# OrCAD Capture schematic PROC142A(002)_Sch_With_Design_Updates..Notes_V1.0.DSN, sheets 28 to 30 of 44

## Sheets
28 27. XDS110 DEBUGGER: size C; title: XDS110 DEBUGGER
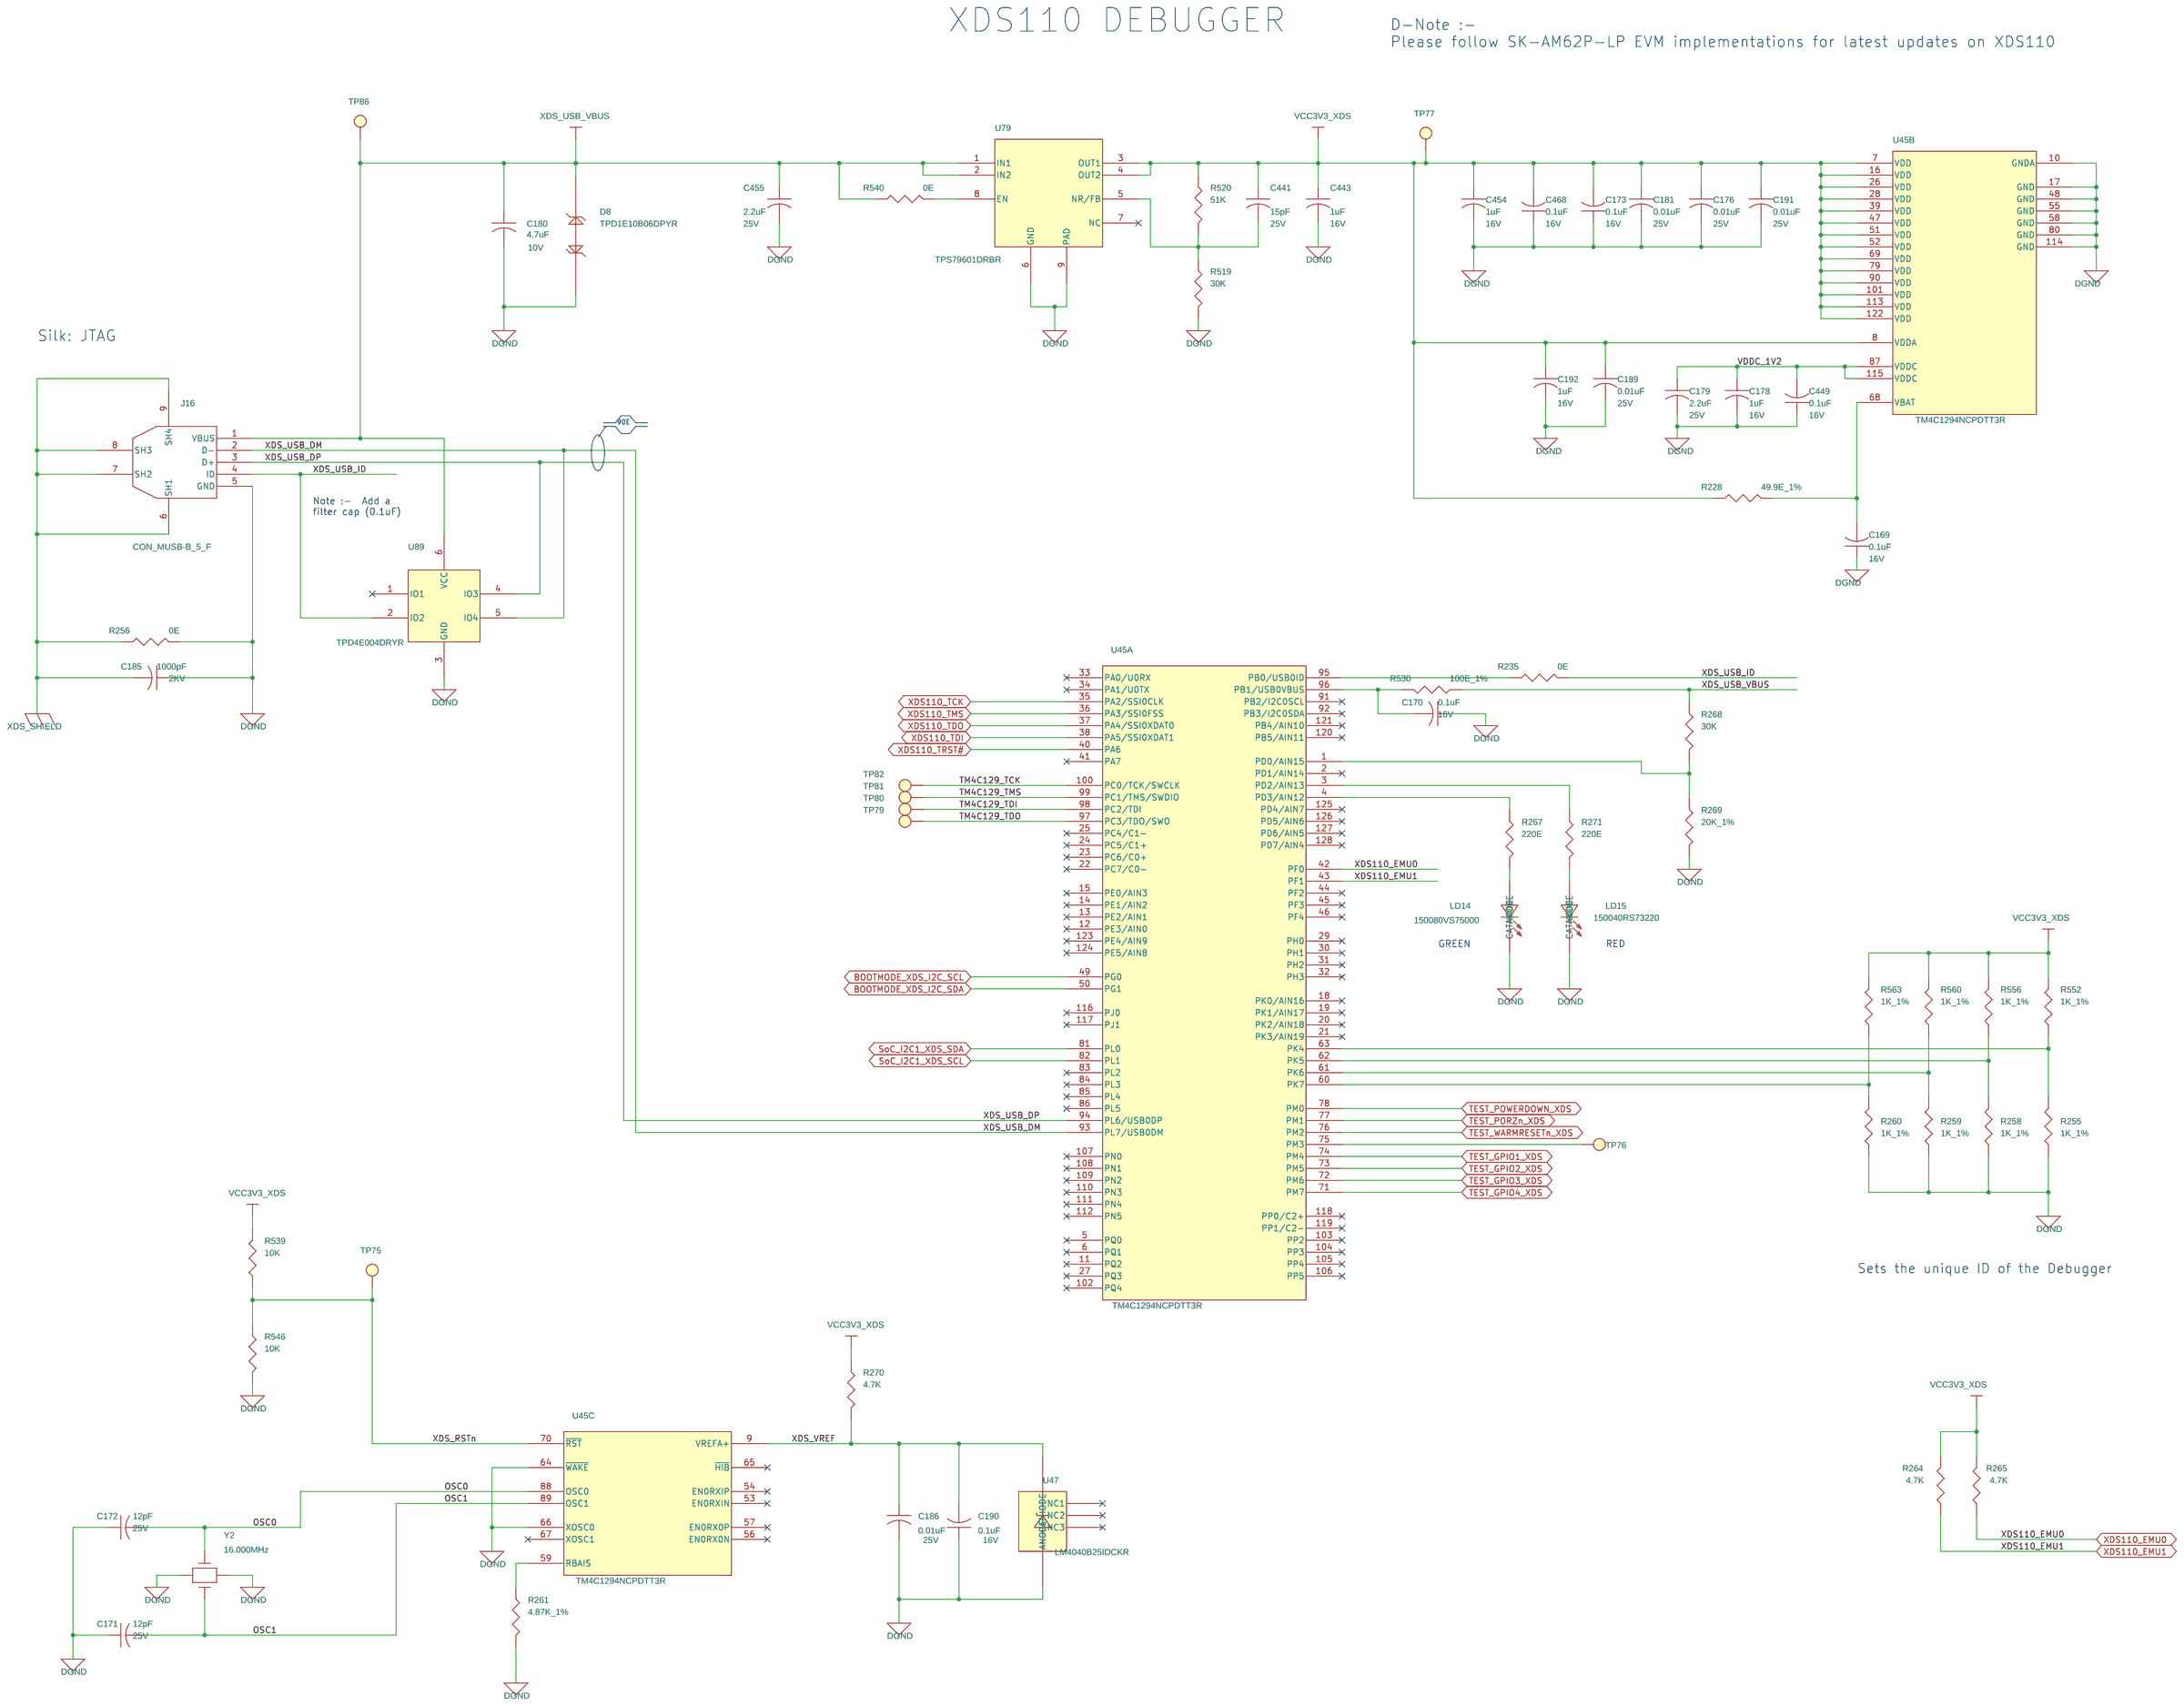
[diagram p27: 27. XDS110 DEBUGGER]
29 29. JTAG BUFFER: size C; title: JTAG BUFFER
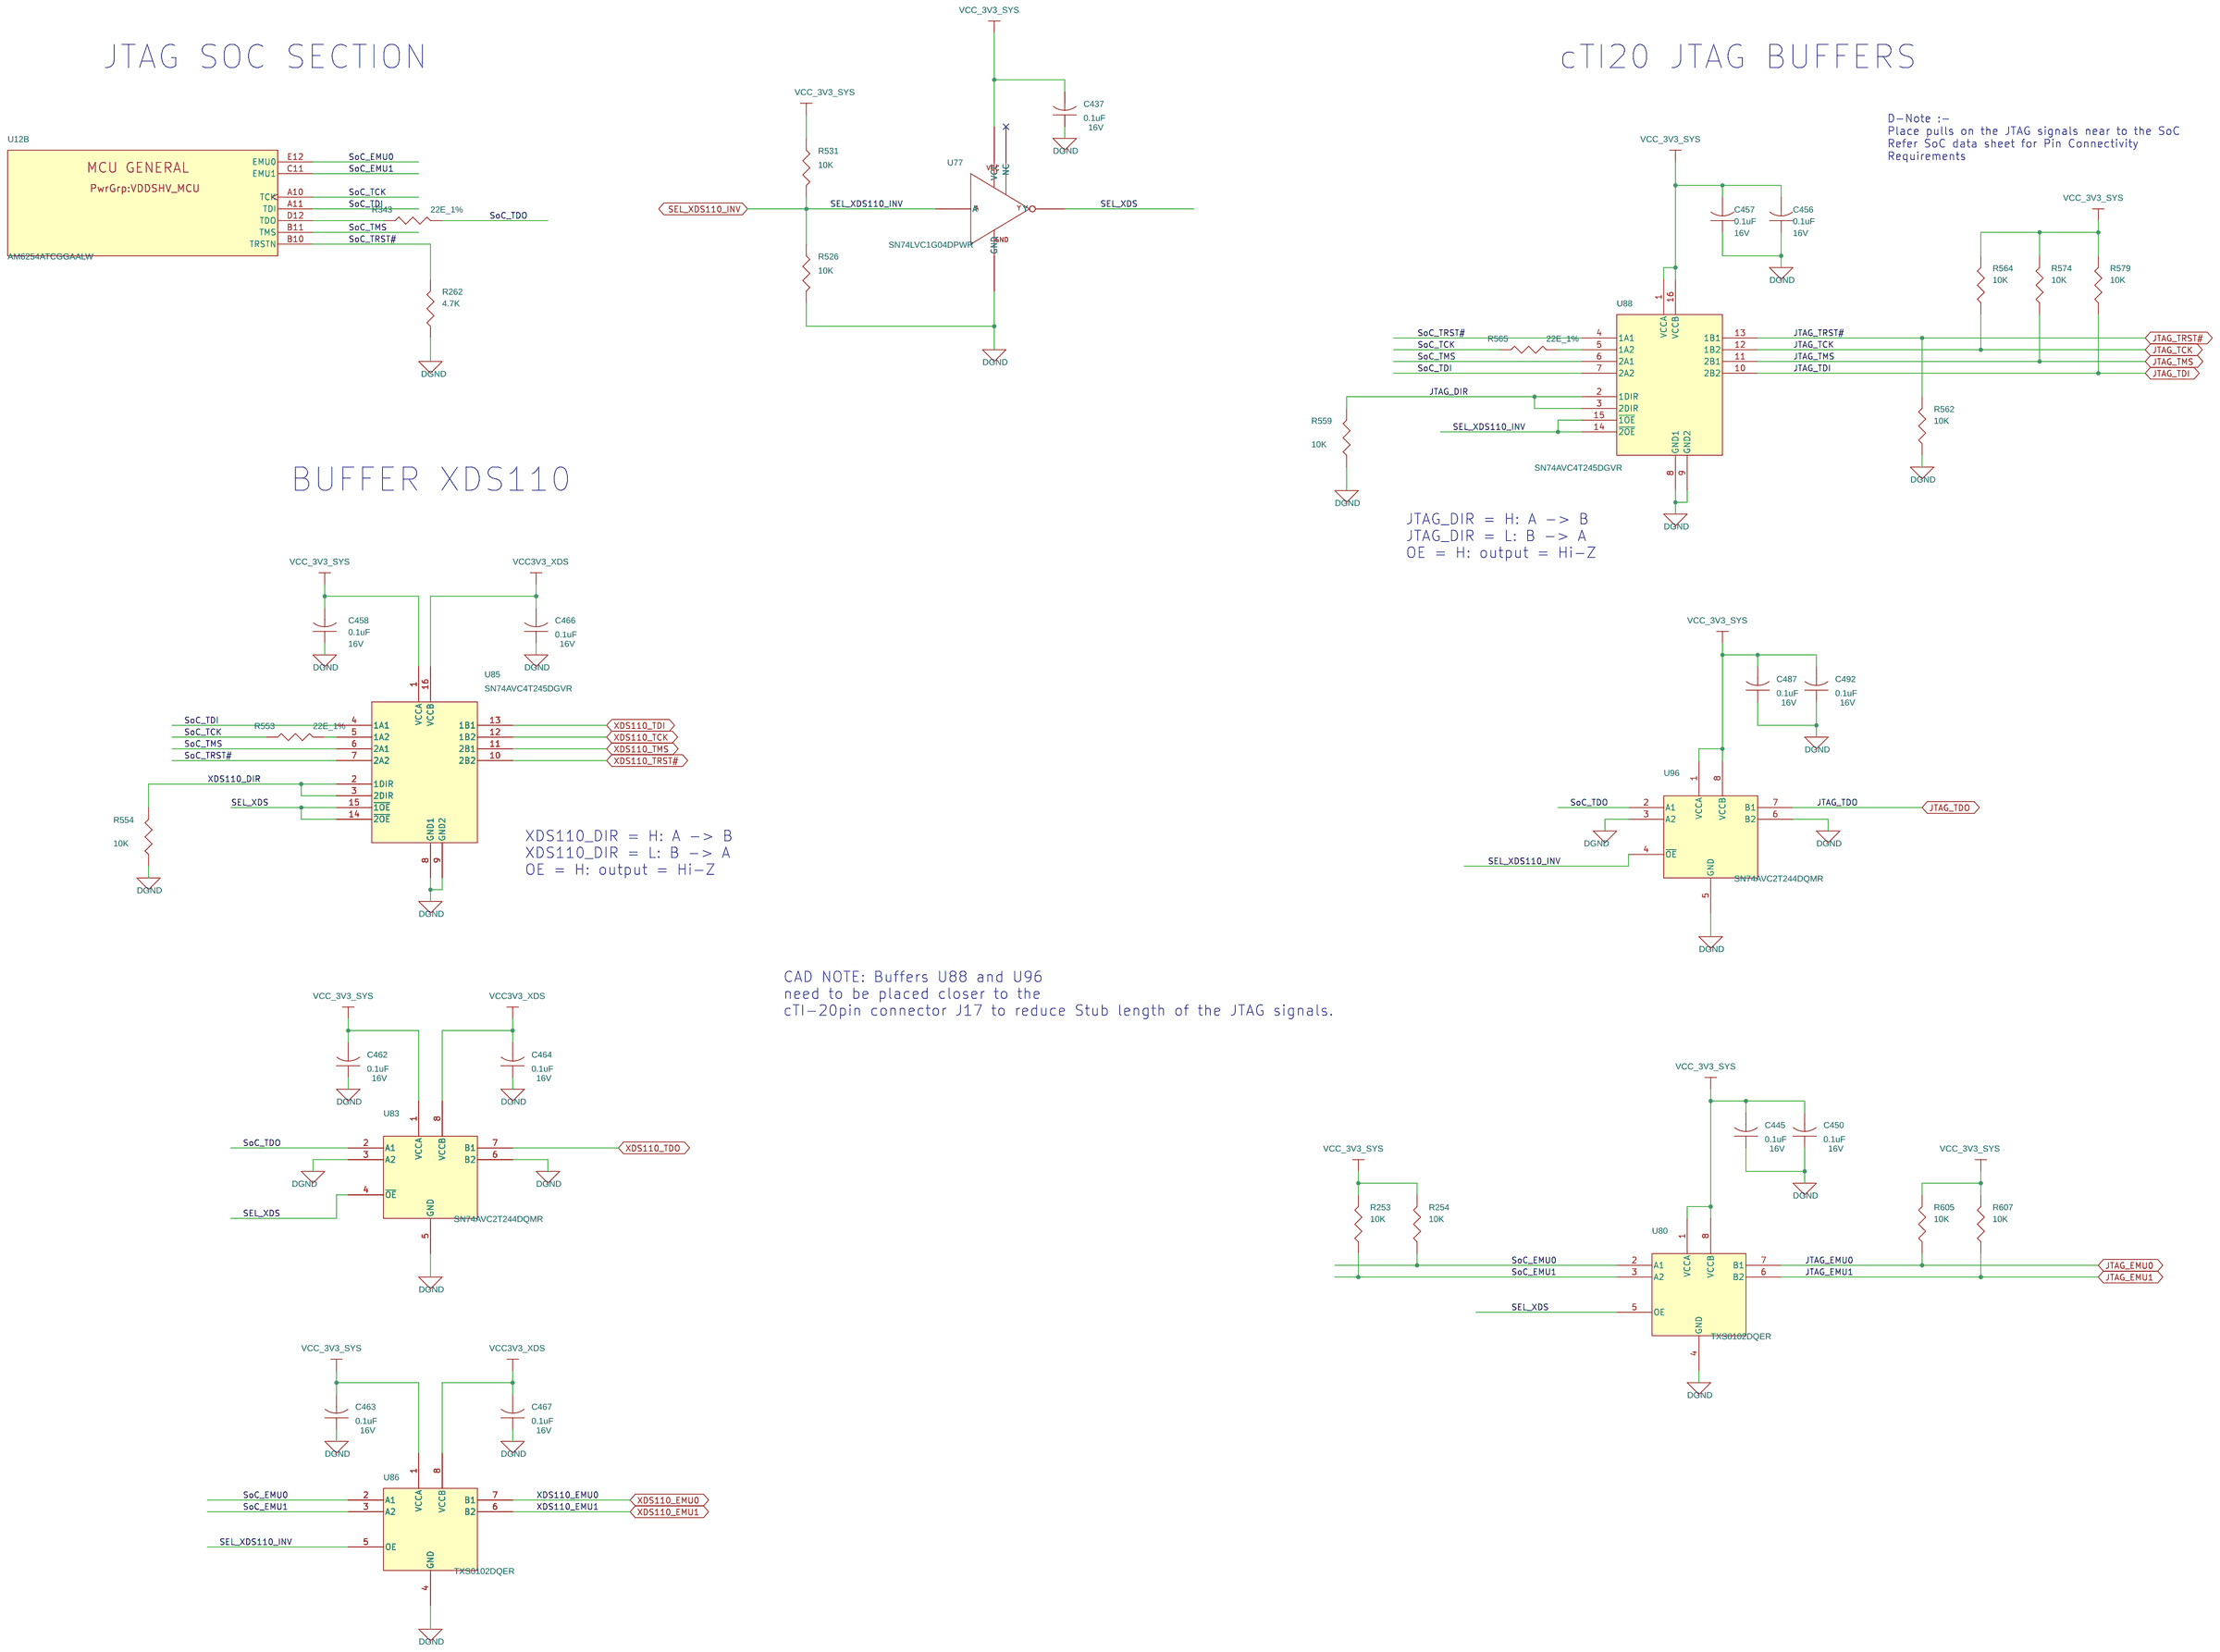
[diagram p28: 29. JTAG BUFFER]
30 30. JTAG 20 PIN cTI CONNECTOR: size C; title: JTAG 20 PIN cTI CONNECTOR
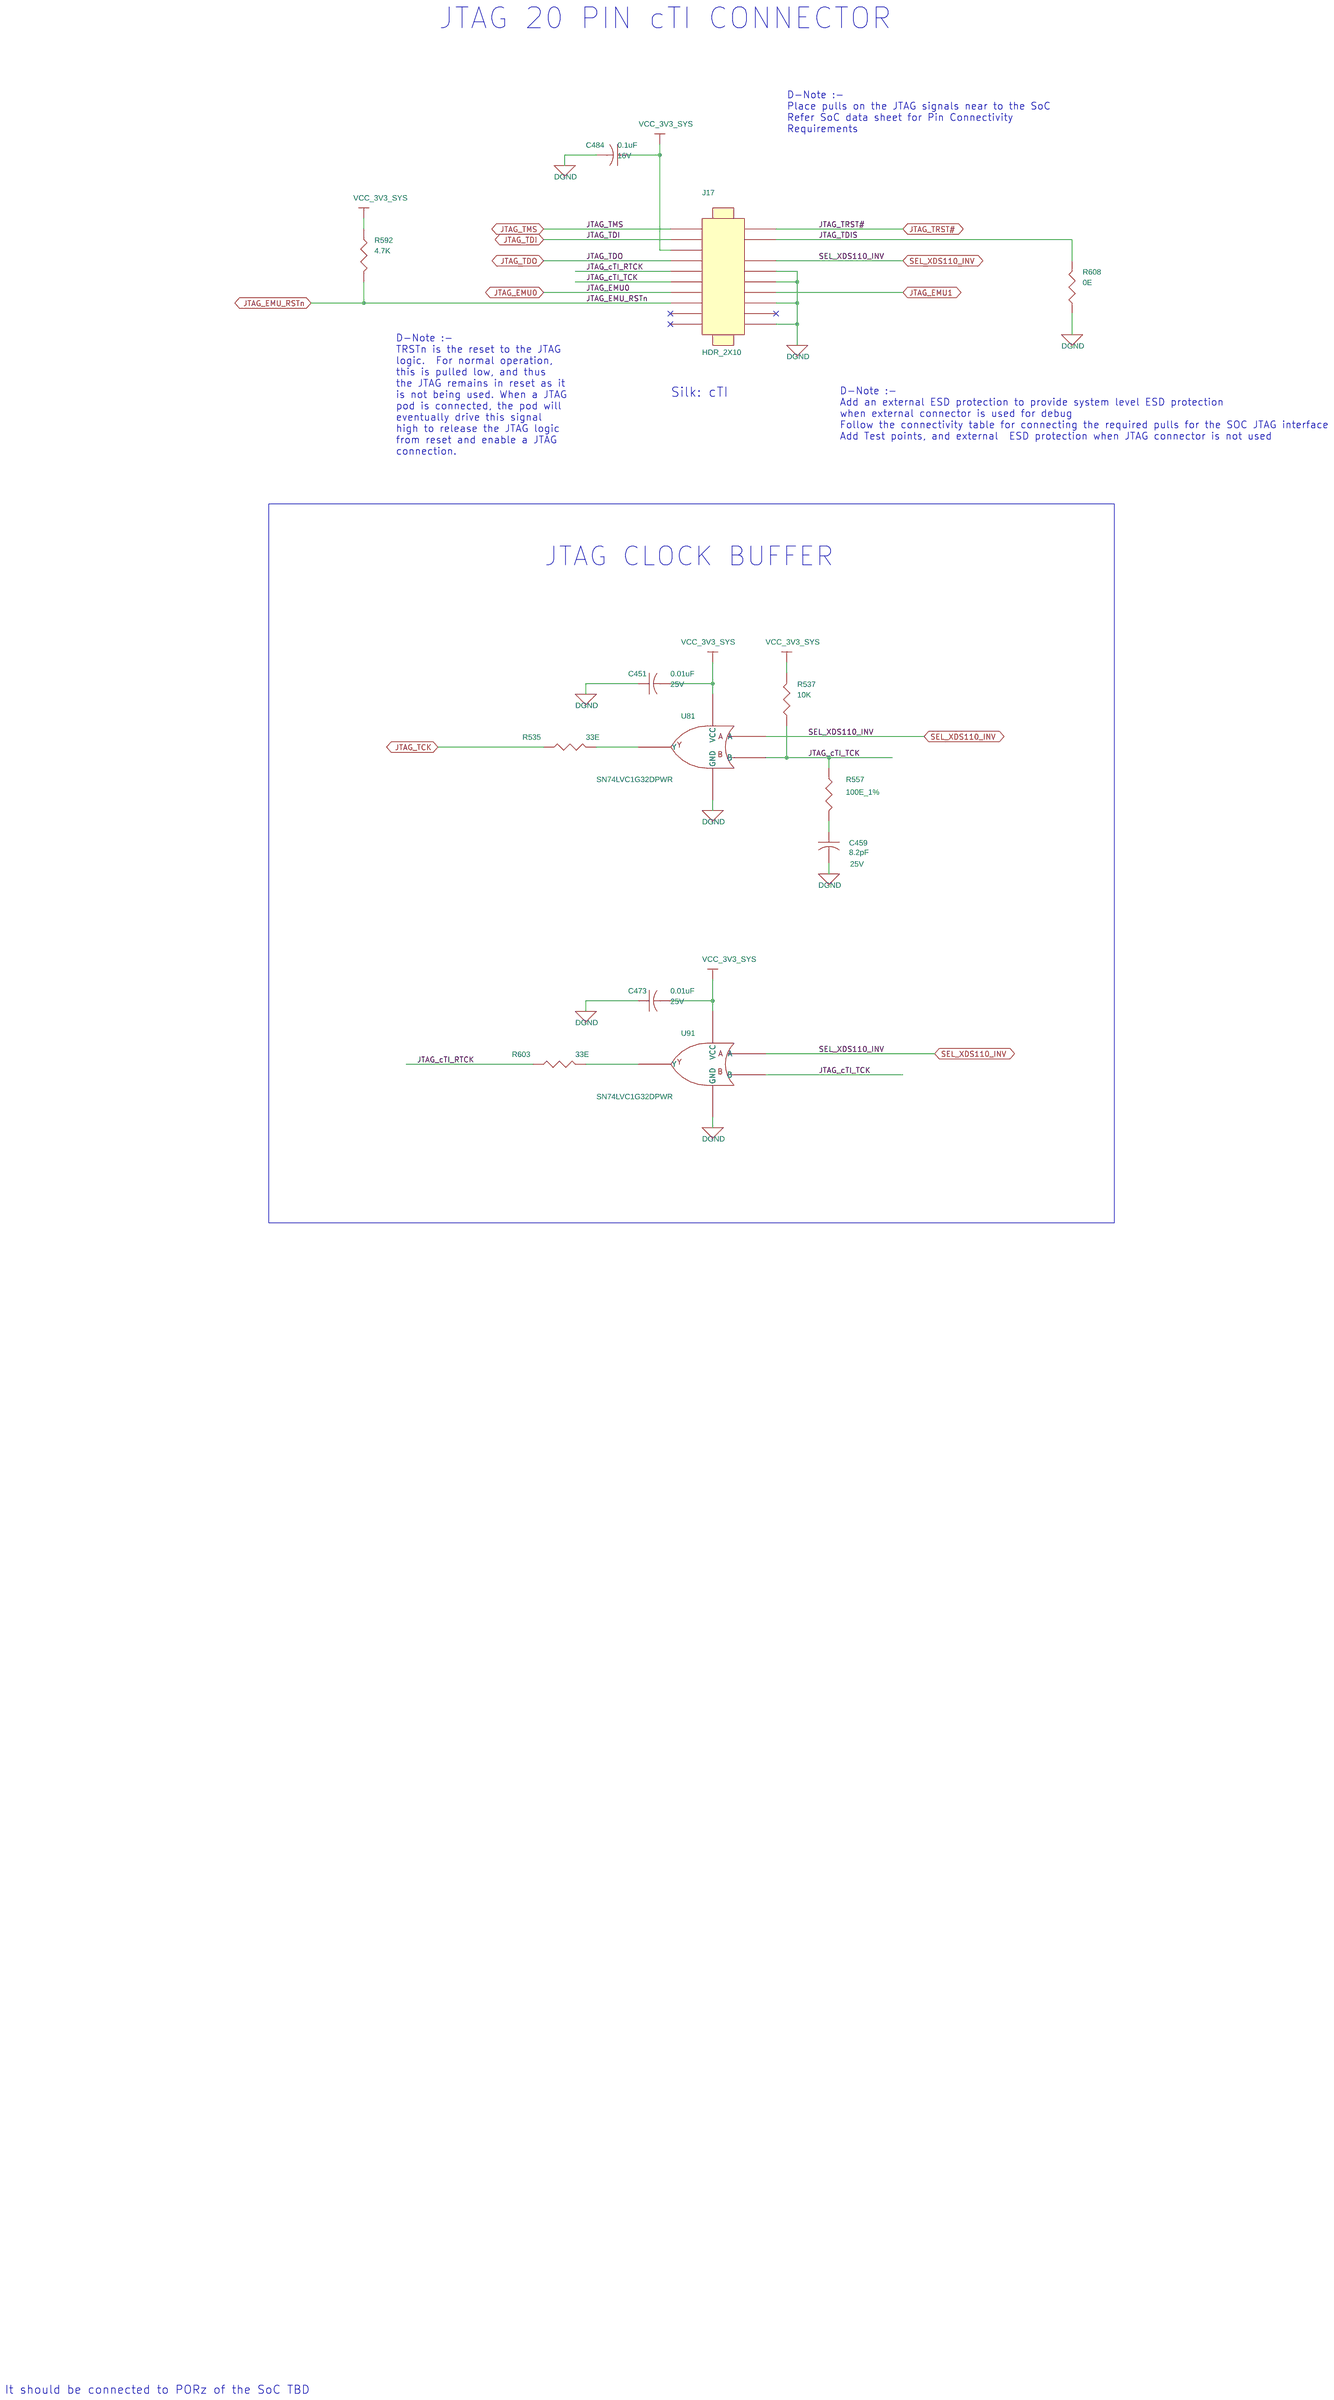
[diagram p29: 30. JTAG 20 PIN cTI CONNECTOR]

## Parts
sheet 27. XDS110 DEBUGGER
C169  0.1uF  [CAP0201_0-5]
C170  0.1uF  [CAP0201_0-5]
C171  12pF  [CAP0201_0-5]
C172  12pF  [CAP0201_0-5]
C173  0.1uF  [CAP0201_0-5]
C176  0.01uF  [CAP0201_0-5]
C178  1uF  [CAP0201_0-5]
C179  2.2uF  [CAP0402_0-75]
C180  4.7uF  [CAP0402_0-75]
C181  0.01uF  [CAP0201_0-5]
C185  1000pF  [CAP1206_1-75]
C186  0.01uF  [CAP0201_0-5]
C189  0.01uF  [CAP0201_0-5]
C190  0.1uF  [CAP0201_0-5]
C191  0.01uF  [CAP0201_0-5]
C192  1uF  [CAP0201_0-5]
C441  15pF  [CAP0201_0-5]
C443  1uF  [CAP0201_0-5]
C449  0.1uF  [CAP0201_0-5]
C454  1uF  [CAP0201_0-5]
C455  2.2uF  [CAP0402_0-75]
C468  0.1uF  [CAP0201_0-5]
D8  TPD1E10B06DPYR  [DIO_DFN0402_0-5]
J16  CON_MUSB-B_5_F  [CON_MUSBB5_629105150521_S_R_S_2-7]
LD14  150080VS75000  [LED_150080VS75000_80X50_SMD_0-8]
LD15  150040RS73220  [LED_150040GS73220_40X20_SMD_0-4]
R228  49.9E_1%  [RES0402_0-5]
R235  0E  [RES0402_0-5]
R255  1K_1%  [RES0402_0-5]
R256  0E  [RES0603_0-75]
R258  1K_1%  [RES0402_0-5]
R259  1K_1%  [RES0402_0-5]
R260  1K_1%  [RES0402_0-5]
R261  4.87K_1%  [RES0402]
R264  4.7K  [RES0201_0-5]
R265  4.7K  [RES0201_0-5]
R267  220E  [RES0402_0-5]
R268  30K  [RES0402_0-5]
R269  20K_1%  [RES0402_0-5]
R270  4.7K  [RES0201_0-5]
R271  220E  [RES0402_0-5]
R519  30K  [RES0402_0-5]
R520  51K  [RES0402_0-5]
R530  100E_1%  [RES0402_0-5]
R539  10K  [RES0201_0-5]
R540  0E  [RES0201_0-5]
R546  10K  [RES0201_0-5]
R552  1K_1%  [RES0402_0-5]
R556  1K_1%  [RES0402_0-5]
R560  1K_1%  [RES0402_0-5]
R563  1K_1%  [RES0402_0-5]
TP75  TP20_SMD  [TP20_SMD]
TP76  TP20_SMD  [TP20_SMD]
TP77  TP20_SMD  [TP20_SMD]
TP79  TP20_SMD  [TP20_SMD]
TP80  TP20_SMD  [TP20_SMD]
TP81  TP20_SMD  [TP20_SMD]
TP82  TP20_SMD  [TP20_SMD]
TP86  TP20_SMD  [TP20_SMD]
U45  TM4C1294NCPDTT3R  [TQFP128_15-74_550X550_1-2]  (sections A,B,C)
U47  LM4040B25IDCKR  [SC70-5_1-1]
U79  TPS79601DRBR  [SON8_25-59_130X130_1]
U89  TPD4E004DRYR  [SON6_19-68_40X60_PB_0-6]
Y2  16.000MHz  [XTAL4_XRCGB-FM_80X60_SMD_0-7]
sheet 29. JTAG BUFFER
C437  0.1uF  [CAP0201_0-5]
C445  0.1uF  [CAP0201_0-5]
C450  0.1uF  [CAP0201_0-5]
C456  0.1uF  [CAP0201_0-5]
C457  0.1uF  [CAP0201_0-5]
C458  0.1uF  [CAP0201_0-5]
C462  0.1uF  [CAP0201_0-5]
C463  0.1uF  [CAP0201_0-5]
C464  0.1uF  [CAP0201_0-5]
C466  0.1uF  [CAP0201_0-5]
C467  0.1uF  [CAP0201_0-5]
C487  0.1uF  [CAP0201_0-5]
C492  0.1uF  [CAP0201_0-5]
R253  10K  [RES0201_0-5]
R254  10K  [RES0201_0-5]
R262  4.7K  [RES0201_0-5]
R343  22E_1%  [RES0201_0-5]
R526  10K  [RES0201_0-5]
R531  10K  [RES0201_0-5]
R553  22E_1%  [RES0201_0-5]
R554  10K  [RES0201_0-5]
R559  10K  [RES0201_0-5]
R562  10K  [RES0201_0-5]
R564  10K  [RES0201_0-5]
R565  22E_1%  [RES0201_0-5]
R574  10K  [RES0201_0-5]
R579  10K  [RES0201_0-5]
R605  10K  [RES0201_0-5]
R607  10K  [RES0201_0-5]
U77  SN74LVC1G04DPWR  [X2SON5_TLV7021_30X30_0-4]
U80  TXS0102DQER  [X2SON8_TXS0102_40X60_0-4]
U83  SN74AVC2T244DQMR  [X2SON8_15-74_70X50]
U85  SN74AVC4T245DGVR  [TVSOP16_15-74_150X180]
U86  TXS0102DQER  [X2SON8_TXS0102_40X60_0-4]
U88  SN74AVC4T245DGVR  [TVSOP16_15-74_150X180]
U96  SN74AVC2T244DQMR  [X2SON8_15-74_70X50]
sheet 30. JTAG 20 PIN cTI CONNECTOR
C451  0.01uF  [CAP0201_0-5]
C459  8.2pF  [CAP0201_0-5]
C473  0.01uF  [CAP0201_0-5]
C484  0.1uF  [CAP0201_0-5]
J17  HDR_2X10  [HDR_2X10_FTR-110-51-D-06_S_S_8-7]
R535  33E  [RES0201_0-5]
R537  10K  [RES0201_0-5]
R557  100E_1%  [RES0402_0-5]
R592  4.7K  [RES0201_0-5]
R603  33E  [RES0201_0-5]
R608  0E  [RES0201_0-5]
U81  SN74LVC1G32DPWR  [X2SON5_TLV7021_30X30_0-4]
U91  SN74LVC1G32DPWR  [X2SON5_TLV7021_30X30_0-4]
sheet 42. OSCILLATOR
U12  AM6254ATCGGAALW  [BGA425_19-68_510X510_0-7]  (sections A,B,C,D,E,F,G,H,I,J,K,L,M,N,O,P,Q,R)

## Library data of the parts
C169 C170 C173 C190 C437 C445 C449 C450 C456-C458 C462-C464 C466-C468 C484 C487 C492 = CAP: CAP CERAMIC 0.1uF 16V 10% X5R 0201; Alt_Mfr_name: YAGEO AMERICA; Alt_Mfr_part_number: CC0402KRX5R8BB104; Chkd/date: MANIRAJA/230118; Crtd /date: MANIRAJA/230118; Custom_Duty: 15%; Customs_HS_Code: 85322990; Distributor_name: DIGIKEY; Distributor_part_number: 490-14305-1-ND; Footprint Path: Y:\MIS_DATABASE\Library\ALTIUM_TOOL\PCB_FOOTPRINTS\Altium_Footprint_Lib.PcbLib; Height: 0.33MM; Library Path: Y:\MIS_DATABASE\Library\ALTIUM_TOOL\SCHEMATICS_PARTS\MS_DISCRETE_Library.schlib; Mfr_name: MURATA; Mfr_part_number: GRM033R61C104KE14D; Mistral Part No: 120009030072-R; Package: 0201; Part_type: CAPACITORS\CERAMIC; Project: TI_MAXIE_CPB; RoHS: RoHS; Temperature: -55°C+85°C; Tolerance: 10%; Voltage: 16V; Wattage: NA; Weight: 0.33mg; Datasheet: Y:\MIS_DATABASE\DATASHEETS\CAPACITORS\GRM033R61C104KE14.PDF
C171 C172 = CAP: CAP CERAMIC 12pF 25V 5% C0G(NP0) 0201; Chkd/date: MANIRAJA/020620; Crtd /date: ALVY/300520; Custom_Duty: 15%; Customs_HS_Code: 85322990; Distributor_name: DIGIKEY; Distributor_part_number: 490-3144-1-ND; Footprint Path: Y:\MIS_DATABASE\Library\ALTIUM_TOOL\PCB_FOOTPRINTS\Altium_Footprint_Lib.PcbLib; Height: 0.33MM; Library Path: Y:\MIS_DATABASE\Library\ALTIUM_TOOL\SCHEMATICS_PARTS\MS_DISCRETE_Library.schlib; Mfr_name: MURATA; Mfr_part_number: GRM0335C1E120JA01D; Mistral Part No: 120009030213-R; Package: 0201; Part_type: CAPACITORS\CERAMIC; Project: QCS610_NANOSOM; RoHS: RoHS; Temperature: -55°C+125°C; Tolerance: 5%; Voltage: 25V; Wattage: NA; Weight: 0.33mg; Datasheet: Y:\MIS_DATABASE\DATASHEETS\CAPACITORS\GRM0335C1E120JA01.PDF
C176 C181 C186 C189 C191 C451 C473 = CAP: CAP CERAMIC 0.01uF 25V 10% X5R 0201; Chkd/date: MANIRAJA/230118; Crtd /date: MANIRAJA/230118; Custom_Duty: 15%; Customs_HS_Code: 85322990; Distributor_name: DIGIKEY; Distributor_part_number: GRM033R61E103KA12J-ND; Footprint Path: Y:\MIS_DATABASE\Library\ALTIUM_TOOL\PCB_FOOTPRINTS\Altium_Footprint_Lib.PcbLib; Height: 0.33MM; Library Path: Y:\MIS_DATABASE\Library\ALTIUM_TOOL\SCHEMATICS_PARTS\MS_DISCRETE_Library.schlib; Mfr_name: MURATA; Mfr_part_number: GRM033R61E103KA12J; Mistral Part No: 120018010007-R; Package: 0201; Part_type: CAPACITORS\CERAMIC; Project: TI_MAXIE_CPB; RoHS: RoHS; Temperature: -55°C+85°C; Tolerance: 10%; Voltage: 25V; Wattage: NA; Weight: 0.33mg; Datasheet: Y:\MIS_DATABASE\DATASHEETS\CAPACITORS\GRM033R61E103KA12.PDF
C178 C192 C443 C454 = CAP: CAP CERAMIC 1uF 16V 20% X5R 0201; Chkd/date: MANIRAJA/300520; Crtd /date: ALVY/260520; Custom_Duty: 15%; Customs_HS_Code: 85322990; Distributor_name: DIGIKEY; Distributor_part_number: 490-18654-1-ND; Footprint Path: Y:\MIS_DATABASE\Library\ALTIUM_TOOL\PCB_FOOTPRINTS\Altium_Footprint_Lib.PcbLib; Height: 0.39MM; Library Path: Y:\MIS_DATABASE\Library\ALTIUM_TOOL\SCHEMATICS_PARTS\MS_DISCRETE_Library.schlib; Mfr_name: MURATA; Mfr_part_number: GRM033R61C105ME15D; Mistral Part No: 120018090038-R; Package: 0201; Part_type: CAPACITORS\CERAMIC; Project: QCS610_NANOSOM; RoHS: RoHS; Temperature: -55°C+85°C; Tolerance: 20%; Voltage: 16V; Wattage: NA; Weight: 0.33mg; Datasheet: Y:\MIS_DATABASE\DATASHEETS\CAPACITORS\GRM033R61C105ME15.PDF
C179 C455 = CAP: CAP CERAMIC 2.2uF 25V 10% X5R 0402; Chkd/date: ALVY/010721; Crtd /date: MANIRAJA/010721; Custom_Duty: 15%; Customs_HS_Code: 85322990; Distributor_name: DIGIKEY; Distributor_part_number: 490-12703-1-ND; Footprint Path: Y:\MIS_DATABASE\Library\ALTIUM_TOOL\PCB_FOOTPRINTS\Altium_Footprint_Lib.PcbLib; Height: 0.70MM; Library Path: Y:\MIS_DATABASE\Library\ALTIUM_TOOL\SCHEMATICS_PARTS\MS_DISCRETE_Library.schlib; Mfr_name: MURATA; Mfr_part_number: GRM155R61E225KE11D; Mistral Part No: 120015120001-R; Package: 0402; Part_type: CAPACITORS\CERAMIC; Project: TI_AM263X_CC; RoHS: RoHS; Temperature: -55°C+85°C; Tolerance: 10%; Voltage: 25V; Wattage: NA; Weight: 1.5mg; Datasheet: Y:\MIS_DATABASE\DATASHEETS\CAPACITORS\GRM155R61E225KE11.PDF
C180 = CAP: CAP CERAMIC 4.7uF 10V 20% X5R 0402; Chkd/date: MANIRAJA/110718; Crtd /date: ALVY/110718; Custom_Duty: 15%; Customs_HS_Code: 85322990; Distributor_name: DIGIKEY; Distributor_part_number: 490-14306-1-ND; Footprint Path: Y:\MIS_DATABASE\Library\ALTIUM_TOOL\PCB_FOOTPRINTS\Altium_Footprint_Lib.PcbLib; Height: 0.65MM; Library Path: Y:\MIS_DATABASE\Library\ALTIUM_TOOL\SCHEMATICS_PARTS\MS_DISCRETE_Library.schlib; Mfr_name: MURATA; Mfr_part_number: GRM155R61A475MEAAD; Mistral Part No: 120012060002-R; Package: 0402; Part_type: CAPACITORS\CERAMIC; Project: TI_J7SVB_PCIE_ADD-ON-CARD; RoHS: RoHS; Temperature: -55°C+85°C; Tolerance: 20%; Voltage: 10V; Wattage: NA; Weight: 14mg; Datasheet: Y:\MIS_DATABASE\DATASHEETS\CAPACITORS\GRM155R61A475MEAAD.PDF
C185 = CAP: CAP CERAMIC 1000pF 2KV 10% X7R 1206; Chkd/date: SHREESHAIL/291106; Crtd /date: MAZHAR/281106; Custom_Duty: 15%; Customs_HS_Code: 85322990; Distributor_name: DIGIKEY; Distributor_part_number: 478-2956-1-ND; Footprint Path: Y:\MIS_DATABASE\Library\ALTIUM_TOOL\PCB_FOOTPRINTS\Altium_Footprint_Lib.PcbLib; Height: 1.52MM; Library Path: Y:\MIS_DATABASE\Library\ALTIUM_TOOL\SCHEMATICS_PARTS\MS_DISCRETE_Library.schlib; Mfr_name: AVX CORPORATION; Mfr_part_number: 1206GC102KAT1A; Mistral Part No: 120015080006-R; Package: 1206; Part_type: CAPACITORS\CERAMIC; Project: ADR1B; RoHS: RoHS; Temperature: -55°C+125°C; Tolerance: 10%; Voltage: 2KV; Wattage: NA; Weight: 16.2mg; Datasheet: Y:\MIS_DATABASE\DATASHEETS\CAPACITORS\AVX_HV-MLC.PDF
C441 = CAP: CAP CERAMIC 15pF 25V 2% HI-Q C0G(NP0) 0201; Chkd/date: VASANTHA/081216; Crtd /date: MANIRAJA/081216; Custom_Duty: 15%; Customs_HS_Code: 85322990; Distributor_name: DIGIKEY; Distributor_part_number: 490-10562-1-ND; Footprint Path: Y:\MIS_DATABASE\Library\ALTIUM_TOOL\PCB_FOOTPRINTS\Altium_Footprint_Lib.PcbLib; Height: 0.33MM; Library Path: Y:\MIS_DATABASE\Library\ALTIUM_TOOL\SCHEMATICS_PARTS\MS_DISCRETE_Library.schlib; Mfr_name: MURATA; Mfr_part_number: GJM0335C1E150GB01D; Mistral Part No: 120016120011-R; Package: 0201; Part_type: CAPACITORS\CERAMIC; Project: OCTBTS5200; RoHS: RoHS; Temperature: -55°C+125°C; Tolerance: 2%; Voltage: 25V; Wattage: NA; Weight: 0.33mg; Datasheet: Y:\MIS_DATABASE\DATASHEETS\CAPACITORS\MURATA-GXX-SER_NOV17.PDF
D8 = DIODE_SOD323: DIODE 1CH ESD PROTECTION X1SON2; Chkd/date: MANIRAJA/040420; Crtd /date: VASANTHA/181114; Custom_Duty: 15%; Customs_HS_Code: 85423100; Distributor_name: DIGIKEY; Distributor_part_number: 296-30406-1-ND; Footprint Path: Y:\MIS_DATABASE\Library\ALTIUM_TOOL\PCB_FOOTPRINTS\Altium_Footprint_Lib.PcbLib; Height: 0.45MM; Library Path: Y:\MIS_DATABASE\Library\ALTIUM_TOOL\SCHEMATICS_PARTS\MS_DISCRETE_Library.schlib; Mfr_name: TEXAS INSTRUMENTS; Mistral Part No: 130014110022-R; Package: X1SON2; Part_type: DIODE; Project: GALILEO_EVM; RoHS: RoHS; Temperature: -40°C+125°C; Tolerance: NA; Voltage: NA; Wattage: NA; Weight: 1mg; Datasheet: Y:\MIS_DATABASE\DATASHEETS\ICS\INTERFACE\TPD1E10B06-SER.PDF
J16 = CON_USB_MINI-B: CON MICRO USB TYPE B 5POS FEMALE RT SMD; Chkd/date: MANIRAJA/150519; Crtd /date: ALVY/150519; Custom_Duty: 24%; Customs_HS_Code: 85369090; Distributor_name: DIGIKEY; Distributor_part_number: 732-5960-1-ND; Footprint Path: Y:\MIS_DATABASE\Library\ALTIUM_TOOL\PCB_FOOTPRINTS\Altium_Footprint_Lib.PcbLib; Height: 2.66MM; Library Path: Y:\MIS_DATABASE\Library\ALTIUM_TOOL\SCHEMATICS_PARTS\MS_CONNECTOR_Library.schlib; Mfr_name: WURTH ELECTRONICS; Mfr_part_number: 629105150521; Mistral Part No: 150019050015-R; Package: SMD; Part_type: CONNECTOR\USB; Project: NEXTNAV_ALT-STATION_ATE_BRD; RoHS: RoHS; Temperature: -40°C+85°C; Tolerance: NA; Voltage: NA; Wattage: NA; Weight: 360mg; Datasheet: Y:\MIS_DATABASE\DATASHEETS\CONNECTORS\629105150521.PDF
LD14 = DIODE_LED: DIODE LED BRIGHT GREEN SMD; Chkd/date: MANIRAJA/180820; Crtd /date: ALVY/180820; Custom_Duty: 24%; Customs_HS_Code: 85439000; Distributor_name: DIGIKEY; Distributor_part_number: 732-4986-1-ND; Footprint Path: Y:\MIS_DATABASE\Library\ALTIUM_TOOL\PCB_FOOTPRINTS\Altium_Footprint_Lib.PcbLib; Height: 0.80MM; Library Path: Y:\MIS_DATABASE\Library\ALTIUM_TOOL\SCHEMATICS_PARTS\MS_OPTO_Library.schlib; Mfr_name: WURTH ELECTRONICS; Mistral Part No: 130020080012-R; Package: SMD; Part_type: OPTO\LED; Project: AM64x_EVM_BRD; RoHS: RoHS; Temperature: -40°C+85°C; Tolerance: NA; Voltage: NA; Wattage: NA; Weight: 10mg; Datasheet: Y:\MIS_DATABASE\DATASHEETS\DISCRETES\LEDS\150080VS75000.PDF
LD15 = DIODE_LED: DIODE LED RED SMD; Chkd/date: MANIRAJA/100920; Crtd /date: ALVY/100920; Custom_Duty: 24%; Customs_HS_Code: 85439000; Distributor_name: DIGIKEY; Distributor_part_number: 732-13422-1-ND; Footprint Path: Y:\MIS_DATABASE\Library\ALTIUM_TOOL\PCB_FOOTPRINTS\Altium_Footprint_Lib.PcbLib; Height: 0.35MM; Library Path: Y:\MIS_DATABASE\Library\ALTIUM_TOOL\SCHEMATICS_PARTS\MS_OPTO_Library.schlib; Mfr_name: WURTH ELECTRONICS; Mistral Part No: 130020090020-R; Package: SMD; Part_type: OPTO\LED; Project: AM64X_SKEVM; RoHS: RoHS; Temperature: -40°C+85°C; Tolerance: NA; Voltage: NA; Wattage: NA; Weight: 29.3mg; Datasheet: Y:\MIS_DATABASE\DATASHEETS\DISCRETES\LEDS\150040RS73220.PDF
R228 = RESISTOR: RES 49.9E 1/16W 1% 0402; Chkd/date: MANIRAJA/210519; Crtd /date: MANIRAJA/210519; Custom_Duty: 15%; Customs_HS_Code: 85332119; Distributor_name: DIGIKEY; Distributor_part_number: 541-3967-1-ND; Footprint Path: Y:\MIS_DATABASE\Library\ALTIUM_TOOL\PCB_FOOTPRINTS\Altium_Footprint_Lib.PcbLib; Height: 0.35MM; Library Path: Y:\MIS_DATABASE\Library\ALTIUM_TOOL\SCHEMATICS_PARTS\MS_DISCRETE_Library.schlib; Mfr_name: VISHAY; Mfr_part_number: CRCW040249R9FKEDC; Mistral Part No: 110009030846-R; Package: 0402; Part_type: RESISTORS\FIXED; Project: RFSU_RFTJ_CARD; RoHS: RoHS; Temperature: -55°C+155°C; Tolerance: 1%; Voltage: NA; Wattage: 1/16W; Weight: 0.65mg; Datasheet: Y:\MIS_DATABASE\DATASHEETS\RESISTORS\CRCW_C-SER.PDF
R235 = RESISTOR: RES 0E 1/16W JUMPER 0402; Chkd/date: VASANTHA/201216; Crtd /date: MUDDU/190810; Custom_Duty: 15%; Customs_HS_Code: 85332119; Distributor_name: DIGIKEY; Distributor_part_number: 541-0.0JCT-ND; Footprint Path: Y:\MIS_DATABASE\Library\ALTIUM_TOOL\PCB_FOOTPRINTS\Altium_Footprint_Lib.PcbLib; Height: 0.40MM; Library Path: Y:\MIS_DATABASE\Library\ALTIUM_TOOL\SCHEMATICS_PARTS\MS_DISCRETE_Library.schlib; Mfr_name: VISHAY; Mfr_part_number: CRCW04020000Z0ED; Mistral Part No: 110010080019-R; Package: 0402; Part_type: RESISTORS\FIXED; Project: PB_BUGBASE; RoHS: RoHS; Temperature: -55°C+155°C; Tolerance: NA; Voltage: NA; Wattage: 1/16W; Weight: 0.65mg; Datasheet: Y:\MIS_DATABASE\DATASHEETS\RESISTORS\CRCW0603.PDF
R255 R258-R260 R552 R556 R560 R563 = RESISTOR: RES 1K 1/10W 1% 0402; Chkd/date: VASANTHA/281216; Crtd /date: MAZHAR/150506; Custom_Duty: 15%; Customs_HS_Code: 85332119; Distributor_name: DIGIKEY; Distributor_part_number: P1.00KLCT-ND; Footprint Path: Y:\MIS_DATABASE\Library\ALTIUM_TOOL\PCB_FOOTPRINTS\Altium_Footprint_Lib.PcbLib; Height: 0.40MM; Library Path: Y:\MIS_DATABASE\Library\ALTIUM_TOOL\SCHEMATICS_PARTS\MS_DISCRETE_Library.schlib; Mfr_name: PANASONIC-ECG; Mfr_part_number: ERJ-2RKF1001X; Mistral Part No: 110009030411-R; Package: 0402; Part_type: RESISTORS\FIXED; Project: VOCERA; RoHS: RoHS; Temperature: -55°C+155°C; Tolerance: 1%; Voltage: NA; Wattage: 1/10W; Weight: 0.8mg; Datasheet: Y:\MIS_DATABASE\DATASHEETS\RESISTORS\PAN-ERJSER_NOV17.PDF
R256 = RESISTOR: RES 0E 1/10W 5% 0603; Chkd/date: MANIRAJA/051217; Crtd /date: BAVISH/180211; Custom_Duty: 15%; Customs_HS_Code: 85332119; Distributor_name: DIGIKEY; Distributor_part_number: 311-0.0GRCT-ND; Footprint Path: Y:\MIS_DATABASE\Library\ALTIUM_TOOL\PCB_FOOTPRINTS\Altium_Footprint_Lib.PcbLib; Height: 0.55MM; Library Path: Y:\MIS_DATABASE\Library\ALTIUM_TOOL\SCHEMATICS_PARTS\MS_DISCRETE_Library.schlib; Manufacturer: YAGEO AMERICA; Mfr_name: PANASONIC-ECG; Mfr_part_number: RC0603JR-070RL; Mistral Part No: 110011020013-R; Package: 0603; Part_type: RESISTORS\FIXED; Project: KENNEL; RoHS: RoHS; Temperature: -55°C+155°C; Tolerance: 5%; Voltage: NA; Wattage: 1/10W; Weight: 2mg; Datasheet: Y:\MIS_DATABASE\DATASHEETS\RESISTORS\RCXXXXL-SER_MAR18.PDF
R261 = RESISTOR: RES 4.87K 1/16W 1% 0402; Chkd/date: MAZHAR/150709; Crtd /date: USMAN/150109; Custom_Duty: 15%; Customs_HS_Code: 85332119; Distributor_name: DIGIKEY; Distributor_part_number: P4.87KLCT-ND; Footprint Path: Y:\MIS_DATABASE\Library\ALTIUM_TOOL\PCB_FOOTPRINTS\Altium_Footprint_Lib.PcbLib; Height: 0.40MM; Library Path: Y:\MIS_DATABASE\Library\ALTIUM_TOOL\SCHEMATICS_PARTS\MS_DISCRETE_Library.schlib; Mfr_name: PANASONIC-ECG; Mfr_part_number: ERJ2RKF4871X; Mistral Part No: 110009030803-R; Package: 0402; Part_type: RESISTORS\FIXED; Project: BSN-II; RoHS: RoHS; Temperature: -55°C+155°C; Tolerance: 1%; Voltage: NA; Wattage: 1/16W; Weight: 0.8mg; Datasheet: Y:\MIS_DATABASE\DATASHEETS\RESISTORS\PAN-ERJSERIES.PDF
R262 R264 R265 R270 R592 = RESISTOR: RES 4.7K 1/20W 5% 0201; Chkd/date: MANIRAJA/200921; Crtd /date: ALVY/200921; Custom_Duty: 15%; Customs_HS_Code: 85332119; Distributor_name: DIGIKEY; Distributor_part_number: 311-4.7KNCT-ND; Footprint Path: Y:\MIS_DATABASE\Library\ALTIUM_TOOL\PCB_FOOTPRINTS\Altium_Footprint_Lib.PcbLib; Height: 0.26MM; Library Path: Y:\MIS_DATABASE\Library\ALTIUM_TOOL\SCHEMATICS_PARTS\MS_DISCRETE_Library.schlib; Mfr_name: YAGEO AMERICA; Mfr_part_number: RC0201JR-074K7L; Mistral Part No: 110021090007-R; Package: 0201; Part_type: RESISTORS\FIXED; Project: TI_AM62x SKEVM_BRD; RoHS: RoHS; Temperature: -55°C+125°C; Tolerance: 5%; Voltage: NA; Wattage: 1/20W; Weight: 0.17mg; Datasheet: Y:\MIS_DATABASE\DATASHEETS\RESISTORS\RCXXXXL-SER_MAR18.PDF
R267 R271 = RESISTOR: RES 220E 1/10W 5% 0402; Chkd/date: VASANTHA/291216; Crtd /date: GEETHA/260406; Custom_Duty: 15%; Customs_HS_Code: 85332119; Distributor_name: DIGIKEY; Distributor_part_number: P220JCT-ND; Footprint Path: Y:\MIS_DATABASE\Library\ALTIUM_TOOL\PCB_FOOTPRINTS\Altium_Footprint_Lib.PcbLib; Height: 0.40MM; Library Path: Y:\MIS_DATABASE\Library\ALTIUM_TOOL\SCHEMATICS_PARTS\MS_DISCRETE_Library.schlib; Mfr_name: PANASONIC-ECG; Mfr_part_number: ERJ-2GEJ221X; Mistral Part No: 110009030506-R; Package: 0402; Part_type: RESISTORS\FIXED; Project: RED EYE; RoHS: RoHS; Temperature: -55°C+155°C; Tolerance: 5%; Voltage: NA; Wattage: 1/10W; Weight: 0.8mg; Datasheet: Y:\MIS_DATABASE\DATASHEETS\RESISTORS\PAN-ERJSER_NOV17.PDF
R268 R519 = RESISTOR: RES 30K 1/16W 5% 0402; Chkd/date: MANIRAJA/230817; Crtd /date: MANIRAJA/230817; Custom_Duty: 15%; Customs_HS_Code: 85332119; Distributor_name: DIGIKEY; Distributor_part_number: 541-30KJCT-ND; Footprint Path: Y:\MIS_DATABASE\Library\ALTIUM_TOOL\PCB_FOOTPRINTS\Altium_Footprint_Lib.PcbLib; Height: 0.40MM; Library Path: Y:\MIS_DATABASE\Library\ALTIUM_TOOL\SCHEMATICS_PARTS\MS_DISCRETE_Library.schlib; Mfr_name: VISHAY; Mfr_part_number: CRCW040230K0JNED; Mistral Part No: 110017080023-R; Package: 0402; Part_type: RESISTORS\FIXED; Project: TI_MAXIE_CPB; RoHS: RoHS; Temperature: -55°C+155°C; Tolerance: 5%; Voltage: NA; Wattage: 1/16W; Weight: 0.65mg; Datasheet: Y:\MIS_DATABASE\DATASHEETS\RESISTORS\CRCW0603.PDF
R269 = RESISTOR: RES 20K 1/16W 1% 0402; Chkd/date: MANIRAJA/021120; Crtd /date: MANIRAJA/021120; Custom_Duty: 15%; Customs_HS_Code: 85332119; Distributor_name: DIGIKEY; Distributor_part_number: 541-20.0KLCT-ND; Footprint Path: Y:\MIS_DATABASE\Library\ALTIUM_TOOL\PCB_FOOTPRINTS\Altium_Footprint_Lib.PcbLib; Height: 0.40MM; Library Path: Y:\MIS_DATABASE\Library\ALTIUM_TOOL\SCHEMATICS_PARTS\MS_DISCRETE_Library.schlib; Mfr_name: VISHAY; Mfr_part_number: CRCW040220K0FKED; Mistral Part No: 110009030486-R; Package: 0402; Part_type: RESISTORS\FIXED; Project: VAGG_SBC_BRD; RoHS: RoHS; Temperature: -55°C+155°C; Tolerance: 1%; Voltage: NA; Wattage: 1/16W; Weight: 0.65mg; Datasheet: Y:\MIS_DATABASE\DATASHEETS\RESISTORS\CRCW0603.PDF
R520 = RESISTOR: RES 51K 1/16W 5% 0402; Chkd/date: MANIRAJA/230817; Crtd /date: MANIRAJA/230817; Custom_Duty: 15%; Customs_HS_Code: 85332119; Distributor_name: DIGIKEY; Distributor_part_number: 541-51KJCT-ND; Footprint Path: Y:\MIS_DATABASE\Library\ALTIUM_TOOL\PCB_FOOTPRINTS\Altium_Footprint_Lib.PcbLib; Height: 0.40MM; Library Path: Y:\MIS_DATABASE\Library\ALTIUM_TOOL\SCHEMATICS_PARTS\MS_DISCRETE_Library.schlib; Mfr_name: VISHAY; Mfr_part_number: CRCW040251K0JNED; Mistral Part No: 110009030966-R; Package: 0402; Part_type: RESISTORS\FIXED; Project: TI_MAXIE_CPB; RoHS: RoHS; Temperature: -55°C+155°C; Tolerance: 5%; Voltage: NA; Wattage: 1/16W; Weight: 0.65mg; Datasheet: Y:\MIS_DATABASE\DATASHEETS\RESISTORS\CRCW0603.PDF
R530 R557 = RESISTOR: RES 100E 1/16W 1% 0402; Chkd/date: MANIRAJA/060318; Crtd /date: NAVEED/220714; Custom_Duty: 15%; Customs_HS_Code: 85332119; Distributor_name: DIGIKEY; Distributor_part_number: 311-100LRCT-ND; Footprint Path: Y:\MIS_DATABASE\Library\ALTIUM_TOOL\PCB_FOOTPRINTS\Altium_Footprint_Lib.PcbLib; Height: 0.40MM; Library Path: Y:\MIS_DATABASE\Library\ALTIUM_TOOL\SCHEMATICS_PARTS\MS_DISCRETE_Library.schlib; Mfr_name: YAGEO AMERICA; Mfr_part_number: RC0402FR-07100RL; Mistral Part No: 110014070015-R; Package: 0402; Part_type: RESISTORS\FIXED; Project: DLRU; RoHS: RoHS; Temperature: -55°C+155°C; Tolerance: 1%; Voltage: NA; Wattage: 1/16W; Weight: 0.65mg; Datasheet: Y:\MIS_DATABASE\DATASHEETS\RESISTORS\RCXXXXL-SER_MAR18.PDF
R253 R254 R526 R531 R537 R539 R546 R554 R559 R562 R564 R574 R579 R605 R607 = RESISTOR: RES 10K 1/20W 5% 0201; Chkd/date: MANIRAJA/050517; Crtd /date: MANIRAJA/050517; Custom_Duty: 15%; Customs_HS_Code: 85332119; Distributor_name: DIGIKEY; Distributor_part_number: 311-10KNCT-ND; Footprint Path: Y:\MIS_DATABASE\Library\ALTIUM_TOOL\PCB_FOOTPRINTS\Altium_Footprint_Lib.PcbLib; Height: 0.26MM; Library Path: Y:\MIS_DATABASE\Library\ALTIUM_TOOL\SCHEMATICS_PARTS\MS_DISCRETE_Library.schlib; Mfr_name: YAGEO AMERICA; Mfr_part_number: RC0201JR-0710KL; Mistral Part No: 110010070051-R; Package: 0201; Part_type: RESISTORS\FIXED; Project: GOLDEN-I LITE; RoHS: RoHS; Temperature: -55°C+125°C; Tolerance: 5%; Voltage: NA; Wattage: 1/20W; Weight: 0.17mg; Datasheet: Y:\MIS_DATABASE\DATASHEETS\RESISTORS\RCXXXXL-SER_MAR18.PDF
R540 R608 = RESISTOR: RES 0E 1/20W 5% 0201; Chkd/date: NAVEED/301214; Crtd /date: MUDDU/120710; Custom_Duty: 15%; Customs_HS_Code: 85332119; Distributor_name: DIGIKEY; Distributor_part_number: 311-0.0NCT-ND; Footprint Path: Y:\MIS_DATABASE\Library\ALTIUM_TOOL\PCB_FOOTPRINTS\Altium_Footprint_Lib.PcbLib; Height: 0.26MM; Library Path: Y:\MIS_DATABASE\Library\ALTIUM_TOOL\SCHEMATICS_PARTS\MS_DISCRETE_Library.schlib; Mfr_name: YAGEO AMERICA; Mfr_part_number: RC0201JR-070RL; Mistral Part No: 110010070067-R; Package: 0201; Part_type: RESISTORS\FIXED; Project: PB_BUGBASE; RoHS: RoHS; Temperature: -55°C+125°C; Tolerance: 5%; Voltage: NA; Wattage: 1/20W; Weight: 0.17mg; Datasheet: Y:\MIS_DATABASE\DATASHEETS\RESISTORS\RCXXXXL-SER_MAR18.PDF
TP75-TP77 TP79-TP82 TP86 = TESTPOINT: TESTPOINT CIR 20 SMD; Chkd/date: SHREESHAIL/171006; Crtd /date: MAZHAR/171006; Custom_Duty: NA; Customs_HS_Code: NA; Distributor_name: NA; Distributor_part_number: NA; Footprint Path: Y:\MIS_DATABASE\Library\ALTIUM_TOOL\PCB_FOOTPRINTS\Altium_Footprint_Lib.PcbLib; Height: NA; Library Path: Y:\MIS_DATABASE\Library\ALTIUM_TOOL\SCHEMATICS_PARTS\MS_DISCRETE_Library.schlib; MECHANICAL 3D STEP FILE: NA; Mfr_name: LOCAL; Mistral Part No: NA; Package: SMD; Project: BT MODULE_CSRBC04; RoHS: NA; Temperature: NA; Tolerance: NA; Voltage: NA; Wattage: NA; Weight: NA; Datasheet: NA
U45 = TM4C1294NCPDTT3R_TQFP128: IC 32-BIT MICROCONTROLLER WITH 1MB FLASH TQFP128; Chkd/date: MANIRAJA/220817; Crtd /date: MANIRAJA/220817; Custom_Duty: 15%; Customs_HS_Code: 85423100; Distributor_name: DIGIKEY; Distributor_part_number: TM4C1294NCPDTT3R-ND; Height: 1.20MM; Mfr_name: TEXAS INSTRUMENTS; Mistral Part No: 141217080002-R; Package: TQF9128; Part_type: ICS\DIGITAL\MICROCONTROLLER; Project: TI_MAXIE_CPB; RoHS: RoHS; Temperature: -40°C+105°C; Tolerance: NA; Voltage: NA; Wattage: NA; Weight: 503.5mg; Datasheet: Y:\MIS_DATABASE\DATASHEETS\ICS\DIGITAL\MICROCONTROLLER\TM4C1294NCPD.PDF
U47 = LM4040B25IDCKR_SC70-5: IC PRECISION MICROPOWER SHUNT VOLTAGE REFERENCE SC70-5; Chkd/date: MANIRAJA/230817; Crtd /date: MANIRAJA/230817; Custom_Duty: 15%; Customs_HS_Code: 85423100; Distributor_name: DIGIKEY; Distributor_part_number: 296-20873-1-ND; Height: 1.10MM; Mfr_name: TEXAS INSTRUMENTS; Mistral Part No: 142017080015-R; Package: SC70-5; Part_type: ICS\POWER\VOLTAGE REGULATOR; Project: TI_MAXIE_CPB; RoHS: RoHS; Temperature: -40°C+85°C; Tolerance: NA; Voltage: NA; Wattage: NA; Weight: 30mg; Datasheet: Y:\MIS_DATABASE\DATASHEETS\ICS\POWER\LM4040B25I.PDF
U79 = TPS79601DRBR_SON8: IC 1A HIGH PSRR RF ADJ LDO LINEAR REGULATOR SON8; Chkd/date: MANIRAJA/030518; Crtd /date: MAZHAR/280809; Custom_Duty: 15%; Customs_HS_Code: 85423100; Distributor_name: DIGIKEY; Distributor_part_number: 296-23107-1-ND; Footprint Path: Y:\MIS_DATABASE\Library\ALTIUM_TOOL\PCB_FOOTPRINTS\Altium_Footprint_Lib.PcbLib; Height: 1.00MM; Library Path: Y:\MIS_DATABASE\Library\ALTIUM_TOOL\SCHEMATICS_PARTS\MS_MISCPOWER_Library.schlib; Mfr_name: TEXAS INSTRUMENTS; Mistral Part No: 142009080012-R; Package: SON8; Part_type: ICS\POWER\VOLTAGE REGULATOR; Project: DIO_TXRX; RoHS: RoHS; Temperature: -40°C+125°C; Tolerance: NA; Voltage: NA; Wattage: NA; Weight: 24mg; Datasheet: Y:\MIS_DATABASE\DATASHEETS\MISC\REGULATORS\TPS796XX.PDF
U89 = TPD4E004_SON6: IC 4-CH ESD PROTECTION ARRAY FOR HIGH SPEED DATA INTERFACE SON6; Chkd/date: MANIRAJA/100320; Crtd /date: MUDDU/010310; Custom_Duty: 15%; Customs_HS_Code: 85423100; Distributor_name: DIGIKEY; Distributor_part_number: 296-23618-1-ND; Footprint Path: Y:\MIS_DATABASE\Library\ALTIUM_TOOL\PCB_FOOTPRINTS\Altium_Footprint_Lib.PcbLib; Height: 0.60MM; Library Path: Y:\MIS_DATABASE\Library\ALTIUM_TOOL\SCHEMATICS_PARTS\MS_MISCINTERFACE_Library.schlib; Mfr_name: TEXAS INSTRUMENTS; Mistral Part No: 141010020012-R; Package: SON6; Part_type: ICS\INTERFACE; Project: BUG_BASE-II; RoHS: RoHS; Temperature: -40°C+85°C; Tolerance: NA; Voltage: NA; Wattage: NA; Weight: 3.2mg; Datasheet: Y:\MIS_DATABASE\DATASHEETS\ICS\INTERFACE\TPD4E004-SER.PDF
Y2 = CRY4_13: CRY 16.000MHz 8pF SMD; Chkd/date: MANIRAJA/151020; Crtd /date: ALVY/151020; Custom_Duty: 24%; Customs_HS_Code: 85439000; Distributor_name: DIGIKEY; Distributor_part_number: 490-18283-1-ND; Footprint Path: Y:\MIS_DATABASE\Library\ALTIUM_TOOL\PCB_FOOTPRINTS\Altium_Footprint_Lib.PcbLib; Height: 0.70MM; Library Path: Y:\MIS_DATABASE\Library\ALTIUM_TOOL\SCHEMATICS_PARTS\MS_DISCRETE_Library.schlib; Mfr_name: MURATA; Mfr_part_number: XRCGB16M000FXN01R0; Mistral Part No: 130020100044-R; Package: SMD; Part_type: CRYSTAL; Project: AM64X_SKEVM; RoHS: RoHS; Temperature: -30°C+85°C; Tolerance: NA; Voltage: NA; Wattage: NA; Weight: 195.4mg; Datasheet: Y:\MIS_DATABASE\DATASHEETS\MISC\CRY_OSC\XRCGB16M000FXN01R0.PDF
R343 R553 R565 = RESISTOR: RES 22E 1/20W 1% 0201; Chkd/date: MAZHAR/140709; Crtd /date: MAZHAR/220807; Custom_Duty: 15%; Customs_HS_Code: 85332119; Distributor_name: DIGIKEY; Distributor_part_number: P22.0ABCT-ND; Footprint Path: Y:\MIS_DATABASE\Library\ALTIUM_TOOL\PCB_FOOTPRINTS\Altium_Footprint_Lib.PcbLib; Height: 0.26MM; Library Path: Y:\MIS_DATABASE\Library\ALTIUM_TOOL\SCHEMATICS_PARTS\MS_DISCRETE_Library.schlib; Mfr_name: PANASONIC-ECG; Mfr_part_number: ERJ-1GEF22R0C; Mistral Part No: 110009030522-R; Package: 0201; Part_type: RESISTORS\FIXED; Project: V8TS; RoHS: RoHS; Temperature: -55°C+125°C; Tolerance: 1%; Voltage: NA; Wattage: 1/20W; Weight: 0.15mg; Datasheet: Y:\MIS_DATABASE\DATASHEETS\RESISTORS\PAN-ERJSER_NOV17.PDF
U77 = SN74LVC1G04DCKR_SC70-5: IC SINGLE INVERTER GATE X2SON5; Chkd/date: MANIRAJA/141020; Crtd /date: ALVY/131020; Custom_Duty: 15%; Customs_HS_Code: 85423100; Distributor_name: DIGIKEY; Distributor_part_number: 296-37758-1-ND; Footprint Path: Y:\MIS_DATABASE\Library\ALTIUM_TOOL\PCB_FOOTPRINTS\Altium_Footprint_Lib.PcbLib; Height: 0.40MM; Library Path: Y:\MIS_DATABASE\Library\ALTIUM_TOOL\SCHEMATICS_PARTS\MS_GATE_Library.schlib; Mfr_name: TEXAS INSTRUMENTS; Mistral Part No: 141020100010-R; Package: X2SON5; Part_type: ICS\DIGITAL\GATES; Project: AM64X_SKEVM; RoHS: RoHS; Temperature: -40°C+125°C; Tolerance: NA; Voltage: NA; Wattage: NA; Weight: 0.6mg; Datasheet: Y:\MIS_DATABASE\DATASHEETS\ICS\DIGITAL\GATES\SN74LVC1G04XX.PDF
U80 U86 = TXS0102DQX_SON8: IC 2-BIT BI-DIR VOLTAGE-LEVEL TRANSLATOR FOR OPEN-DRAIN AND PUSH-PULL X2SON8; Chkd/date: MANIRAJA/010719; Crtd /date: CHAITHANYA230512; Custom_Duty: 15%; Customs_HS_Code: 85423100; Distributor_name: DIGIKEY; Distributor_part_number: 296-28368-1-ND; Footprint Path: Y:\MIS_DATABASE\Library\ALTIUM_TOOL\PCB_FOOTPRINTS\Altium_Footprint_Lib.PcbLib; Height: 0.40MM; Library Path: Y:\MIS_DATABASE\Library\ALTIUM_TOOL\SCHEMATICS_PARTS\MS_MISCINTERFACE_Library.schlib; Mfr_name: TEXAS INSTRUMENTS; Mistral Part No: 141012050010-R; Package: X2SON8; Part_type: ICS\INTERFACE\LEVEL TRANSLATOR; Project: GEN_3-8_DB; RoHS: RoHS; Temperature: -40°C+85°C; Tolerance: NA; Voltage: NA; Wattage: NA; Weight: 1.2mg; Datasheet: Y:\MIS_DATABASE\DATASHEETS\ICS\INTERFACE\TXS0102-SER.PDF
U83 U96 = SN74AVC2T244DQMR_X2SON8: IC 2-BIT UNDIRECTIONAL VOLTAGE-LEVEL TRANSLATOR X2SON8; Chkd/date: VASANTHA/060516; Crtd /date: VASANTHA/030316; Customs_HS_Code: 15%; Distributor_name: DIGIKEY; Distributor_part_number: 296-29674-1-ND; Height: 0.40MM; Mfr_name: TEXAS INSTRUMENTS; Mistral Part No: 141016030002-R; Package: X2SON8; Part_type: ICS\INTERFACE\LEVEL TRANSLATOR; Pb-Free: 85423100; Project: OCTASIC_3600; RoHS: RoHS; Temperature: -40°C+85°C; Tolerance: NA; Voltage: NA; Wattage: NA; Weight: NA; Datasheet: Y:\MIS_DATABASE\DATASHEETS\ICS\INTERFACE\SN74AVC2T244.PDF
U85 U88 = SN74AVC4T245DGVR_TVSOP16: IC 4-BIT DUAL SUPPLY BUS TRANSCEIVER TVSOP16; Chkd/date: SUHAS/251010; Crtd /date: MAZHAR/201109; Custom_Duty: 15%; Customs_HS_Code: 85423100; Distributor_name: DIGIKEY; Distributor_part_number: 296-18054-1-ND; Height: 1.20MM; Mfr_name: TEXAS INSTRUMENTS; Mistral Part No: 141009110005-P; Package: TVSOP16; Part_type: ICS\DIGITAL\COMBINATIONAL; Project: GOLDEN-I; RoHS: Sb/ Br FREE; Temperature: -40°C+85°C; Datasheet: Y:\MIS_DATABASE\DATASHEETS\ICS\DIGITAL\BUSTRANSCEIVER\SN74AVC4T245.PDF
C459 = CAP: CAP CERAMIC 8.2pF 25V 0.5pF C0G(NP0) 0201; Chkd/date: MANIRAJA/121020; Crtd /date: ALVY/091020; Custom_Duty: 15%; Customs_HS_Code: 85322990; Distributor_name: DIGIKEY; Distributor_part_number: 490-3140-1-ND; Footprint Path: Y:\MIS_DATABASE\Library\ALTIUM_TOOL\PCB_FOOTPRINTS\Altium_Footprint_Lib.PcbLib; Height: 0.33MM; Library Path: Y:\MIS_DATABASE\Library\ALTIUM_TOOL\SCHEMATICS_PARTS\MS_DISCRETE_Library.schlib; Mfr_name: MURATA; Mfr_part_number: GRM0335C1E8R2DA01D; Mistral Part No: 120020100018-R; Package: 0201; Part_type: CAPACITORS\CERAMIC; Project: AM64X_SKEVM; RoHS: RoHS; Temperature: -55°C+125°C; Tolerance: 0.5pF%; Voltage: 25V; Wattage: NA; Weight: 0.33mg; Datasheet: Y:\MIS_DATABASE\DATASHEETS\CAPACITORS\GRM0335C1E8R2DA01.PDF
J17 = HEADER_10X2_FTR-06: CON HDR 2X10 1.27MM PITCH ST SMD; Chkd/date: MANIRAJA/031218; Crtd /date: CHAITHANYA/050811; Custom_Duty: 24%; Customs_HS_Code: 85369090; Distributor_name: DIGIKEY; Distributor_part_number: SAM8792-ND; Footprint Path: Y:\MIS_DATABASE\Library\ALTIUM_TOOL\PCB_FOOTPRINTS\Altium_Footprint_Lib.PcbLib; Height: 8.67MM; Library Path: Y:\MIS_DATABASE\Library\ALTIUM_TOOL\SCHEMATICS_PARTS\MS_CONNECTOR_Library.schlib; Mfr_name: SAMTEC; Mfr_part_number: FTR-110-51-S-D-06; Mistral Part No: 150011090001-R; Package: SMD; Part_type: CONNECTOR\HEADERS; Project: GEMYC; RoHS: RoHS; Temperature: -55°C+125°C; Tolerance: NA; Voltage: NA; Wattage: NA; Weight: NA; Datasheet: Y:\MIS_DATABASE\DATASHEETS\CONNECTORS\FTR-D-SER.PDF
R535 R603 = RESISTOR: RES 33E 1/20W 5% 0201; Chkd/date: VASANTHA/061216; Crtd /date: MAZHAR/170505; Custom_Duty: 15%; Customs_HS_Code: 85332119; Distributor_name: DIGIKEY; Distributor_part_number: P33AGCT-ND; Footprint Path: Y:\MIS_DATABASE\Library\ALTIUM_TOOL\PCB_FOOTPRINTS\Altium_Footprint_Lib.PcbLib; Height: 0.26MM; Library Path: Y:\MIS_DATABASE\Library\ALTIUM_TOOL\SCHEMATICS_PARTS\MS_DISCRETE_Library.schlib; Mfr_name: PANASONIC-ECG; Mfr_part_number: ERJ-1GEJ330C; Mistral Part No: 110010070052-R; Package: 0201; Part_type: RESISTORS\FIXED; Project: G4SLIM; RoHS: RoHS; Temperature: -55°C+125°C; Tolerance: 5%; Voltage: NA; Wattage: 1/20W; Weight: 0.15mg; Datasheet: Y:\MIS_DATABASE\DATASHEETS\RESISTORS\PAN-ERJXGE-FEB06.PDF
U81 U91 = SN74LVC1G32_X2SON5: IC SINGLE 2-INPUT POSITIVE-OR GATE X2SON5; Chkd/date: MANIRAJA/141020; Crtd /date: ALVY/131020; Custom_Duty: 15%; Customs_HS_Code: 85423100; Distributor_name: DIGIKEY; Distributor_part_number: 296-SN74LVC1G32DPWRCT-ND; Footprint Path: Y:\MIS_DATABASE\Library\ALTIUM_TOOL\PCB_FOOTPRINTS\Altium_Footprint_Lib.PcbLib; Height: 0.40MM; Library Path: Y:\MIS_DATABASE\Library\ALTIUM_TOOL\SCHEMATICS_PARTS\MS_GATE_Library.schlib; Mfr_name: TEXAS INSTRUMENTS; Mistral Part No: 141020100011-R; Package: X2SON5; Part_type: ICS\DIGITAL\GATES; Project: AM64X_SKEVM; RoHS: RoHS; Temperature: -40°C+125°C; Tolerance: NA; Voltage: NA; Wattage: NA; Weight: 0.6mg; Datasheet: Y:\MIS_DATABASE\DATASHEETS\ICS\DIGITAL\GATES\SN74LVC1G32XX.PDF
U12 = AM62-EVM_BGA425: IC AM62 SoC MICROPROCESSOR BGA425; Chkd/date: ALVY/110621; Crtd /date: MANIRAJA/110621; Custom_Duty: 15%; Customs_HS_Code: 85423100; Distributor_name: NA; Distributor_part_number: NA; Footprint Path: Y:\MIS_DATABASE\Library\ALTIUM_TOOL\PCB_FOOTPRINTS\Altium_Footprint_Lib.PcbLib; Height: 0.65MM; Library Path: Y:\MIS_DATABASE\Library\ALTIUM_TOOL\SCHEMATICS_PARTS\MS_MICROPROCESSOR_Library.schlib; Mfr_name: TEXAS INSTRUMENTS; Mistral Part No: 141221060001; Package: BGA425; Part_type: ICS\DIGITAL\MICROPROCESSOR; Project: AM62_EVM_BRD; RoHS: NA; Temperature: NA; Tolerance: NA; Voltage: NA; Wattage: NA; Weight: NA; Datasheet: Y:\MIS_DATABASE\DATASHEETS\ICS\DIGITAL\MICROCONTROLLER\AM62-SoC_SVB.PDF

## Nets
DGND: C169.1 C170.1 C171.1 C172.1 C173.1 C176.2 C178.2 C179.2 C180.2 C181.2 C185.1 C186.2 C189.2 C190.1 C191.2 C192.2 C437.1 C443.2 C445.1 C449.1 C450.1 C451.1 C454.2 C455.2 C456.1 C457.1 C458.1 C459.2 C462.1 C463.1 C464.1 C466.1 C467.1 C468.1 C473.1 C484.2 C487.1 C492.1 D8.1 J16.5(GND) J17.10 J17.12 J17.16 J17.20 LD14.1(CATHODE) LD15.1(CATHODE) R255.1 R256.1 R258.1 R259.1 R260.1 R261.2 R262.2 R269.2 R519.2 R526.1 R546.2 R554.1 R559.1 R562.1 R608.1 U45.10(GNDA) U45.17(GND) U45.48(GND) U45.55(GND) U45.58(GND) U45.64(~{WAKE}) U45.66(XOSC0) U45.80(GND) U45.114(GND) U47.1(ANODE) U77.3(GND) U79.6(GND) U79.9(PAD) U80.4(GND) U81.3(GND) U83.3(A2) U83.5(GND) U83.6(B2) U85.8(GND1) U85.9(GND2) U86.4(GND) U88.8(GND1) U88.9(GND2) U89.3(GND) U91.3(GND) U96.3(A2) U96.5(GND) U96.6(B2) Y2.2 Y2.4 ; also on sheet 1 10 11 12 13 14 15 16 17 18 19 20 21 22 23 24 25 26 27 31 32 33 34 35 36 37 38 39 40 41 42 43
VCC3V3_XDS: C173.2 C176.1 C181.1 C189.1 C191.1 C192.1 C441.1 C443.1 C454.1 C464.2 C466.2 C467.2 C468.2 R228.2 R264.1 R265.1 R270.1 R520.1 R539.2 R552.2 R556.2 R560.2 R563.2 TP77.1(TP) U45.7(VDD) U45.8(VDDA) U45.16(VDD) U45.26(VDD) U45.28(VDD) U45.39(VDD) U45.47(VDD) U45.51(VDD) U45.52(VDD) U45.69(VDD) U45.79(VDD) U45.90(VDD) U45.101(VDD) U45.113(VDD) U45.122(VDD) U79.3(OUT1) U79.4(OUT2) U83.8(VCCB) U85.16(VCCB) U86.8(VCCB) ; also on sheet 1
VCC_3V3_SYS: C437.2 C445.2 C450.2 C451.2 C456.2 C457.2 C458.2 C462.2 C463.2 C473.2 C484.1 C487.2 C492.2 J17.5 R253.1 R254.1 R531.2 R537.2 R564.2 R574.2 R579.2 R592.1 R605.1 R607.1 U77.5(VCC) U80.1(VCCA) U80.8(VCCB) U81.5(VCC) U83.1(VCCA) U85.1(VCCA) U86.1(VCCA) U88.1(VCCA) U88.16(VCCB) U91.5(VCC) U96.1(VCCA) U96.8(VCCB) ; also on sheet 10 12 13 14 18 19 20 22 23 24 25 26 27 31 32 33 34 35 36 37 38 39 40 41 42 43
VDDC_1V2: C178.1 C179.1 C449.2 U45.87(VDDC) U45.115(VDDC)
BOOTMODE_XDS_I2C_SCL: U45.49(PG0) ; also on sheet 1
BOOTMODE_XDS_I2C_SDA: U45.50(PG1) ; also on sheet 1
JTAG_cTI_RTCK: J17.9 R603.1
JTAG_cTI_TCK: J17.11 R537.1 R557.1 U81.1(B) U91.1(B)
JTAG_DIR: R559.2 U88.2(1DIR) U88.3(2DIR)
JTAG_EMU0: J17.13 R605.2 U80.7(B1)
JTAG_EMU1: J17.14 R607.2 U80.6(B2)
JTAG_EMU_RSTn: J17.15 R592.2 ; also on sheet 42
JTAG_TCK: R535.1 R564.1 U88.12(1B2)
JTAG_TDI: J17.3 R579.1 U88.10(2B2)
JTAG_TDIS: J17.4 R608.2
JTAG_TDO: J17.7 U96.7(B1)
JTAG_TMS: J17.1 R574.1 U88.11(2B1)
JTAG_TRST#: J17.2 R562.2 U88.13(1B1)
OSC0: C172.2 U45.88(OSC0) Y2.3
OSC1: C171.2 U45.89(OSC1) Y2.1
SEL_XDS: U77.4(Y) U80.5(OE) U83.4(~{OE}) U85.14(~{2OE}) U85.15(~{1OE})
SEL_XDS110_INV: J17.8 R526.2 R531.1 U77.2(A) U81.2(A) U86.5(OE) U88.14(~{2OE}) U88.15(~{1OE}) U91.2(A) U96.4(~{OE})
SoC_EMU0: R254.2 U12.E12(EMU0) U80.2(A1) U86.2(A1)
SoC_EMU1: R253.2 U12.C11(EMU1) U80.3(A2) U86.3(A2)
SoC_I2C1_XDS_SCL: U45.82(PL1) ; also on sheet 1
SoC_I2C1_XDS_SDA: U45.81(PL0) ; also on sheet 1
SoC_TCK: R553.1 R565.1 U12.A10(TCK)
SoC_TDI: U12.A11(TDI) U85.4(1A1) U88.7(2A2)
SoC_TDO: R343.1 U83.2(A1) U96.2(A1)
SoC_TMS: U12.B11(TMS) U85.6(2A1) U88.6(2A1)
SoC_TRST#: R262.1 U12.B10(TRSTN) U85.7(2A2) U88.4(1A1)
TEST_GPIO1_XDS: U45.74(PM4) ; also on sheet 1
TEST_GPIO2_XDS: U45.73(PM5) ; also on sheet 1
TEST_GPIO3_XDS: U45.72(PM6) ; also on sheet 1
TEST_GPIO4_XDS: U45.71(PM7) ; also on sheet 1
TEST_PORZn_XDS: U45.77(PM1) ; also on sheet 1
TEST_POWERDOWN_XDS: U45.78(PM0) ; also on sheet 1
TEST_WARMRESETn_XDS: U45.76(PM2) ; also on sheet 1
TM4C129_TCK: TP82.1(TP) U45.100(PC0/TCK/SWCLK)
TM4C129_TDI: TP80.1(TP) U45.98(PC2/TDI)
TM4C129_TDO: TP79.1(TP) U45.97(PC3/TDO/SWO)
TM4C129_TMS: TP81.1(TP) U45.99(PC1/TMS/SWDIO)
XDS110_DIR: R554.2 U85.2(1DIR) U85.3(2DIR)
XDS110_EMU0: R265.2 U45.42(PF0) U86.7(B1)
XDS110_EMU1: R264.2 U45.43(PF1) U86.6(B2)
XDS110_TCK: U45.35(PA2/SSI0CLK) U85.12(1B2)
XDS110_TDI: U45.38(PA5/SSI0XDAT1) U85.13(1B1)
XDS110_TDO: U45.37(PA4/SSI0XDAT0) U83.7(B1)
XDS110_TMS: U45.36(PA3/SSI0FSS) U85.11(2B1)
XDS110_TRST#: U45.40(PA6) U85.10(2B2)
XDS_RSTn: R539.1 R546.1 TP75.1(TP) U45.70(~{RST})
XDS_SHIELD: C185.2 J16.6(SH1) J16.7(SH2) J16.8(SH3) J16.9(SH4) R256.2
XDS_USB_DM: J16.2(D-) U45.93(PL7/USB0DM) U89.5(IO4)
XDS_USB_DP: J16.3(D+) U45.94(PL6/USB0DP) U89.4(IO3)
XDS_USB_ID: J16.4(ID) R235.2 U89.2(IO2)
XDS_USB_VBUS: C180.1 C455.1 D8.2 J16.1(VBUS) R268.1 R530.1 R540.1 TP86.1(TP) U79.1(IN1) U79.2(IN2) U89.6(VCC)
XDS_VREF: C186.1 C190.2 R270.2 U45.9(VREFA+) U47.3(CATHODE)
N16994873: R535.2 U81.4(Y)
N16994875: R603.2 U91.4(Y)
N16995245: C459.1 R557.2
N16997746: R261.1 U45.59(RBAIS)
N17030548: R343.2 U12.D12(TDO)
N17034231: R565.2 U88.5(1A2)
N17479799: R540.2 U79.8(EN)
N17479805: C441.2 R519.1 R520.2 U79.5(NR/FB)
N17479881: C169.2 R228.1 U45.68(VBAT)
N17481587: LD14.2(ANODE) R267.2
N17481598: C170.2 R530.2 U45.96(PB1/USB0VBUS)
N17481613: R235.1 U45.95(PB0/USB0ID)
N17481619: R268.2 R269.1 U45.1(PD0/AIN15)
N17481621: R260.2 R563.1 U45.60(PK7)
N17481627: R271.1 U45.3(PD2/AIN13)
N17481631: LD15.2(ANODE) R271.2
N17481633: R255.2 R552.1 U45.63(PK4)
N17481635: R259.2 R560.1 U45.61(PK6)
N17481637: R267.1 U45.4(PD3/AIN12)
N17481641: R258.2 R556.1 U45.62(PK5)
N18374561: TP76.1(TP) U45.75(PM3)
N20696645: R553.2 U85.5(1A2)

Not connected (* = marked no-connect by the designer): J17 17* 18* 19*; U45 2(PD1/AIN14)* 5(PQ0)* 6(PQ1)* 11(PQ2)* 12(PE3/AIN0)* 13(PE2/AIN1)* 14(PE1/AIN2)* 15(PE0/AIN3)* 18(PK0/AIN16)* 19(PK1/AIN17)* 20(PK2/AIN18)* 21(PK3/AIN19)* 22(PC7/C0-)* 23(PC6/C0+)* 24(PC5/C1+)* 25(PC4/C1-)* 27(PQ3)* 29(PH0)* 30(PH1)* 31(PH2)* 32(PH3)* 33(PA0/U0RX)* 34(PA1/U0TX)* 41(PA7)* 44(PF2)* 45(PF3)* 46(PF4)* 53(EN0RXIN)* 54(EN0RXIP)* 56(EN0RX0N)* 57(EN0RX0P)* 65(~{HIB})* 67(XOSC1)* 83(PL2)* 84(PL3)* 85(PL4)* 86(PL5)* 91(PB2/I2C0SCL)* 92(PB3/I2C0SDA)* 102(PQ4)* 103(PP2)* 104(PP3)* 105(PP4)* 106(PP5)* 107(PN0)* 108(PN1)* 109(PN2)* 110(PN3)* 111(PN4)* 112(PN5)* 116(PJ0)* 117(PJ1)* 118(PP0/C2+)* 119(PP1/C2-)* 120(PB5/AIN11)* 121(PB4/AIN10)* 123(PE4/AIN9)* 124(PE5/AIN8)* 125(PD4/AIN7)* 126(PD5/AIN6)* 127(PD6/AIN5)* 128(PD7/AIN4)*; U47 2(NC1)* 4(NC2)* 5(NC3)*; U77 1(NC)*; U79 7(NC)*; U89 1(IO1)*

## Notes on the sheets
sheet 28
- XDS110 DEBUGGER
- D-Note :-
  Please follow SK-AM62P-LP EVM implementations for latest updates on XDS110
- Silk: JTAG
- 90E
- Note :-  Add a
  filter cap (0.1uF)
- GREEN
- RED
- Sets the unique ID of the Debugger
sheet 29
- JTAG SOC SECTION
- cTI20 JTAG BUFFERS
- D-Note :-
  Place pulls on the JTAG signals near to the SoC
  Refer SoC data sheet for Pin Connectivity
  Requirements
- BUFFER XDS110
- JTAG_DIR = H: A -> B
  JTAG_DIR = L: B -> A
  OE = H: output = Hi-Z
- XDS110_DIR = H: A -> B
  XDS110_DIR = L: B -> A
  OE = H: output = Hi-Z
- CAD NOTE: Buffers U88 and U96
  need to be placed closer to the
  cTI-20pin connector J17 to reduce Stub length of the JTAG signals.
sheet 30
- JTAG 20 PIN cTI CONNECTOR
- D-Note :-
  Place pulls on the JTAG signals near to the SoC
  Refer SoC data sheet for Pin Connectivity
  Requirements
- D-Note :-
  TRSTn is the reset to the JTAG
  logic.  For normal operation,
  this is pulled low, and thus
  the JTAG remains in reset as it
  is not being used. When a JTAG
  pod is connected, the pod will
  eventually drive this signal
  high to release the JTAG logic
  from reset and enable a JTAG
  connection.
- Silk: cTI
- D-Note :-
  Add an external ESD protection to provide system level ESD protection
  when external connector is used for debug
  Follow the connectivity table for connecting the required pulls for the SOC JTAG interface
  Add Test points, and external  ESD protection when JTAG connector is not used
- JTAG CLOCK BUFFER
- It should be connected to PORz of the SoC TBD
